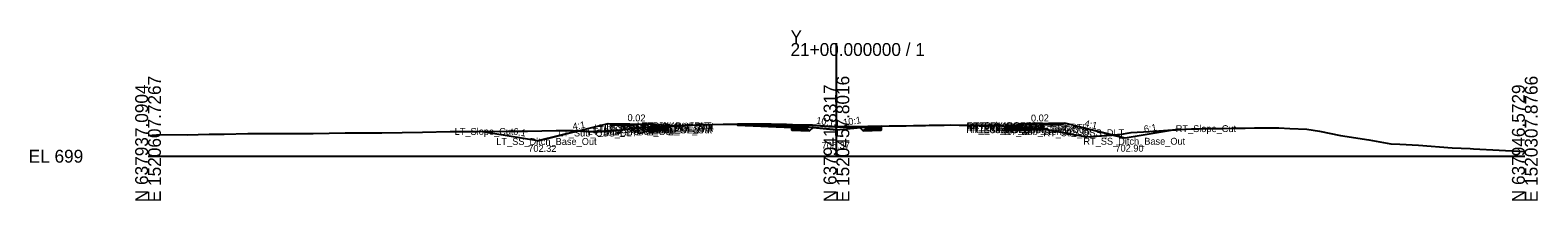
# Model space of a CAD drawing. Extents: x -26 to 303, y -10 to 5039.
# Drawn here: x -25.7 to 302.8, y 4490.3 to 4527.4 of the extents above; entities that cross this region are included whole.
import ezdxf

# ---------------------------------------------------------------- set-up
doc = ezdxf.new("R2010")
doc.units = 0
for name, color, linetype in [('Default', 7, 'Continuous'), ('Exist Cross Section Cell', 7, 'Continuous'), ('Exist XS Center Line Elevation Label', 7, 'Continuous'), ('Exist XS Ground Line', 7, 'Continuous'), ('Prop CMT Pvmt Course 1', 7, 'Continuous'), ('Prop CMT Pvmt Course 2', 7, 'Continuous'), ('Prop CMT Pvmt Course 3', 7, 'Continuous'), ('Prop CMT Pvmt Surface Shoulder', 7, 'Continuous'), ('Prop CMT Shld Paved Course 1', 7, 'Continuous'), ('Prop CMT Shld Paved Course 2', 7, 'Continuous'), ('Prop CMT Shld Paved Course 3', 7, 'Continuous'), ('Prop CMT Slope Grass', 7, 'Continuous'), ('Prop CMT Subgrade Earthwork', 7, 'Continuous'), ('Prop Conc 4in Sidewalk', 7, 'Continuous'), ('Prop XS Ditch Standard Text', 7, 'Continuous'), ('Prop XS Earthwork Shape', 7, 'Continuous'), ('Prop XS Side Slope Text', 7, 'Continuous'), ('Scratch_Level_0', 7, 'Continuous'), ('Typical Curb CELL', 7, 'Continuous'), ('Typical Shoulder Slope Information CELL', 7, 'Continuous')]:
    doc.layers.add(name, color=color, linetype=linetype)

# ---------------------------------------------------------------- blocks, each defined once
blk = doc.blocks.new('2_6 CURB RIGHT')
at = {"layer": 'Typical Curb CELL'}
for p, q in [((0, -0.58), (0, 0)), ((0, 0), (1.75, -0.07)), ((2, 0.17), (2, 0.18)), ((2.5, 0.42), (2.24, 0.42)), ((2.31, 0.08), (2.33, -0.01)), ((2.46, 0.04), (2.31, 0.08)), ((2.33, -0.01), (2.46, 0.04)), ((2.5, -0.58), (2.5, 0.42)), ((2.5, -0.58), (0, -0.58)), ((0.26, -0.34), (0.35, -0.22)), ((0.38, -0.34), (0.26, -0.34)), ((0.35, -0.22), (0.38, -0.34)), ((1.03, -0.39), (1.09, -0.28)), ((1.19, -0.36), (1.03, -0.39)), ((1.09, -0.28), (1.19, -0.36)), ((1.51, -0.34), (1.6, -0.22)), ((1.63, -0.34), (1.51, -0.34)), ((1.6, -0.22), (1.63, -0.34)), ((2.27, -0.39), (2.34, -0.28)), ((2.44, -0.36), (2.27, -0.39)), ((2.34, -0.28), (2.44, -0.36))]:
    blk.add_line(p, q, dxfattribs=at)
for centre in [(2.27, 0.34), (2.43, 0.12), (2.49, 0.31), (0.01, -0.55), (0.02, -0.25), (0.03, -0.15), (0.07, -0.39), (0.09, -0.18), (0.17, -0.34), (0.2, -0.06), (0.22, -0.58), (0.3, -0.14), (0.34, -0.04), (0.38, -0.51), (0.49, -0.1), (0.52, -0.21), (0.59, -0.53), (0.67, -0.29), (0.69, -0.12), (0.7, -0.45), (0.71, -0.07), (0.76, -0.56), (0.79, -0.26), (0.93, -0.5), (0.97, -0.1), (1.09, -0.15), (1.11, -0.54), (1.26, -0.55), (1.27, -0.25), (1.28, -0.15), (1.32, -0.39), (1.34, -0.18), (1.42, -0.34), (1.45, -0.1), (1.47, -0.58), (1.54, -0.14), (1.63, -0.51), (1.74, -0.1), (1.77, -0.21), (1.84, -0.53), (1.92, -0.29), (1.94, -0.12), (1.95, -0.45), (1.96, -0.07), (2.01, -0.56), (2.04, -0.26), (2.18, -0.5), (2.22, -0.1), (2.34, -0.15), (2.35, -0.54)]:
    blk.add_circle(centre, 0.00802, dxfattribs=at)
for centre, start, end in [((1.76, 0.17), 267.6155, 0), ((2.24, 0.18), 90, 180)]:
    blk.add_arc(centre, 0.24, start, end, dxfattribs=at)

msp = doc.modelspace()

# ---------------------------------------------------------------- linework, layer by layer
at = {"layer": 'Exist Cross Section Cell'}
for p, q in [((150, 4500), (150, 4524.61)), ((0, 4500), (150, 4500)), ((150, 4500), (300, 4500))]:
    msp.add_line(p, q, dxfattribs=at)
at = {"layer": 'Exist XS Ground Line'}
msp.add_lwpolyline([(0, 4504.54), (2.72, 4504.71), (8.54, 4504.65), (13.29, 4504.8), (16.55, 4504.83), (21.74, 4504.92), (23.33, 4504.94), (25.09, 4504.94), (36, 4504.94), (42.98, 4505.07), (47.32, 4505.08), (50.96, 4505.1), (59.8, 4505.23), (65.84, 4505.36), (71.63, 4505.4), (78.49, 4505.44), (82.69, 4505.47), (88.9, 4505.58), (92.62, 4505.63), (93.44, 4505.55), (97.09, 4505.29), (100.88, 4505.5), (102.66, 4505.59), (103.48, 4505.72), (107.67, 4506.29), (111.33, 4506.52), (111.72, 4506.54), (112.82, 4506.55), (114.48, 4506.63), (115.17, 4506.63), (117.64, 4506.72), (120.29, 4506.81), (122.9, 4506.89), (125.34, 4506.97), (126.51, 4507), (127.63, 4507), (129.67, 4506.99), (130.12, 4506.98), (130.6, 4506.98), (132.63, 4506.98), (133.21, 4506.97), (135.13, 4506.94), (135.77, 4506.94), (137.63, 4506.92), (138.27, 4506.9), (138.76, 4506.88), (139.15, 4506.87), (140.41, 4506.84), (144.75, 4506.74), (148.25, 4506.5), (149.66, 4506.37), (150, 4506.37), (153.53, 4506.4), (155.77, 4506.4), (156.87, 4506.45), (161.47, 4506.58), (162.07, 4506.58), (162.66, 4506.59), (163.37, 4506.61), (165.18, 4506.63), (166.8, 4506.67), (167.67, 4506.68), (169.38, 4506.71), (170.17, 4506.73), (170.9, 4506.74), (172.66, 4506.77), (173.49, 4506.78), (174.77, 4506.81), (176.73, 4506.78), (177.65, 4506.76), (178.16, 4506.76), (180.15, 4506.74), (182.28, 4506.71), (182.66, 4506.71), (185.23, 4506.67), (186.2, 4506.64), (190.67, 4506.28), (195.28, 4505.91), (202.97, 4504.5), (204.45, 4504.21), (210.31, 4504.63), (211.21, 4504.69), (211.65, 4504.75), (214.25, 4505.13), (218.25, 4505.4), (227.4, 4505.99), (228.06, 4505.99), (228.66, 4505.99), (229.05, 4505.99), (229.84, 4506), (231.08, 4506.01), (231.8, 4506.01), (233.58, 4506.04), (234.23, 4506.05), (236.07, 4506.07), (238.04, 4506.1), (238.57, 4506.11), (239.07, 4506.11), (241.07, 4506.14), (241.43, 4506.15), (243.46, 4506.17), (244.43, 4506.19), (245.49, 4506.19), (246.39, 4506.19), (248.8, 4506.06), (252.52, 4505.88), (255.23, 4505.43), (259.87, 4504.54), (266.01, 4503.59), (270.8, 4502.68), (272.74, 4502.59), (276.85, 4502.38), (284.18, 4501.83), (288.08, 4501.66), (288.82, 4501.62), (300, 4501.02)], dxfattribs=at)
at = {"layer": 'Prop CMT Pvmt Course 1'}
for p, q in [((114, 4506.35), (113.25, 4506.32)), ((114, 4506.35), (114, 4506.6)), ((143.51, 4506.15), (143.25, 4506.41)), ((156.49, 4506.15), (156.75, 4506.41))]:
    msp.add_line(p, q, dxfattribs=at)
for points in [[(113.24, 4506.57), (113.24, 4506.32)], [(113.24, 4506.32), (113.25, 4506.32)], [(113.25, 4506.32), (113.25, 4506.57)], [(140.25, 4506.28), (140.25, 4506.53)], [(159.75, 4506.28), (159.75, 4506.53)], [(186.74, 4506.37), (186.74, 4506.62)]]:
    msp.add_lwpolyline(points, dxfattribs=at)
at = {"layer": 'Prop CMT Pvmt Course 2'}
for points in [[(113.25, 4506.32), (113.24, 4506.32)], [(113.24, 4506.32), (113.24, 4506.07)], [(113.24, 4506.07), (113.25, 4506.07)], [(113.25, 4506.07), (113.25, 4506.32)], [(140.25, 4506.03), (140.25, 4506.28)], [(159.75, 4506.03), (159.75, 4506.28)]]:
    msp.add_lwpolyline(points, dxfattribs=at)
at = {"layer": 'Prop CMT Pvmt Course 3'}
for points in [[(113.25, 4506.07), (113.24, 4506.07)], [(113.24, 4506.07), (113.24, 4505.7)], [(113.24, 4505.7), (113.25, 4505.7)], [(113.25, 4505.7), (113.25, 4506.07)], [(140.25, 4505.66), (140.25, 4506.03)], [(159.74, 4505.65), (159.75, 4505.65)], [(159.75, 4505.66), (159.75, 4506.03)]]:
    msp.add_lwpolyline(points, dxfattribs=at)
at = {"layer": 'Prop CMT Pvmt Surface Shoulder'}
for p, q in [((143.25, 4506.41), (128.41, 4507)), ((156.75, 4506.41), (159.75, 4506.53))]:
    msp.add_line(p, q, dxfattribs=at)
for points in [[(114, 4506.6), (112.24, 4506.53)], [(186.74, 4506.62), (187.75, 4506.58)]]:
    msp.add_lwpolyline(points, dxfattribs=at)
at = {"layer": 'Prop CMT Shld Paved Course 1'}
for points in [[(112.24, 4506.28), (113.25, 4506.32)], [(113.24, 4506.32), (113.24, 4506.57)], [(187.75, 4506.33), (186.74, 4506.37)]]:
    msp.add_lwpolyline(points, dxfattribs=at)
at = {"layer": 'Prop CMT Shld Paved Course 2'}
for p, q in [((143.77, 4505.89), (143.51, 4506.15)), ((156.23, 4505.89), (156.49, 4506.15))]:
    msp.add_line(p, q, dxfattribs=at)
for points in [[(113.25, 4506.32), (112.24, 4506.28)], [(112.24, 4506.03), (113.25, 4506.07)], [(113.24, 4506.07), (113.24, 4506.32)], [(140.25, 4506.28), (143.51, 4506.15)], [(143.77, 4505.89), (140.25, 4506.03)], [(156.23, 4505.89), (159.75, 4506.03)], [(159.75, 4506.28), (156.49, 4506.15)], [(186.74, 4506.37), (187.75, 4506.33)], [(187.75, 4506.08), (186.74, 4506.12)]]:
    msp.add_lwpolyline(points, dxfattribs=at)
at = {"layer": 'Prop CMT Shld Paved Course 3'}
for p, q in [((109.24, 4505.95), (108.81, 4505.52)), ((109.74, 4505.95), (109.24, 4505.95)), ((144.16, 4505.5), (143.77, 4505.89)), ((155.84, 4505.5), (156.23, 4505.89)), ((190.25, 4505.99), (190.75, 4505.99)), ((190.75, 4505.99), (191.18, 4505.57))]:
    msp.add_line(p, q, dxfattribs=at)
for points in [[(108.81, 4505.52), (113.25, 4505.7)], [(113.25, 4506.07), (112.24, 4506.03)], [(113.24, 4505.7), (113.24, 4506.07)], [(140.25, 4506.03), (143.77, 4505.89)], [(144.16, 4505.5), (140.25, 4505.66)], [(155.84, 4505.5), (159.75, 4505.66)], [(159.75, 4506.03), (156.23, 4505.89)], [(186.74, 4506.12), (187.75, 4506.08)], [(191.18, 4505.57), (186.74, 4505.74)]]:
    msp.add_lwpolyline(points, dxfattribs=at)
at = {"layer": 'Prop CMT Slope Grass'}
for p, q in [((84.96, 4503.32), (100.24, 4507.14)), ((100.24, 4507.14), (109.74, 4506.95)), ((150, 4505.74), (143.25, 4506.41)), ((150, 4505.74), (156.75, 4506.41)), ((199.75, 4507.18), (190.25, 4506.99)), ((212.9, 4503.9), (199.75, 4507.18)), ((224.21, 4505.78), (212.9, 4503.9))]:
    msp.add_line(p, q, dxfattribs=at)
msp.add_lwpolyline([(84.96, 4503.32), (72.47, 4505.4)], dxfattribs=at)
at = {"layer": 'Prop CMT Subgrade Earthwork'}
for p, q in [((108.81, 4505.52), (107.34, 4507)), ((109.74, 4505.95), (109.74, 4506.95)), ((112.24, 4505.95), (109.74, 4505.95)), ((112.24, 4506.53), (112.24, 4505.95)), ((114, 4506.35), (113.25, 4506.32)), ((113.25, 4505.7), (113.25, 4506.32)), ((114, 4506.6), (114, 4506.35)), ((128.41, 4506.75), (128.41, 4507)), ((140.25, 4506.28), (128.41, 4506.75)), ((140.25, 4506.28), (140.25, 4505.66)), ((159.75, 4506.53), (159.75, 4505.66)), ((186.74, 4505.74), (186.74, 4506.62)), ((187.75, 4506.58), (190.25, 4506.99)), ((191.18, 4505.57), (192.65, 4507.04))]:
    msp.add_line(p, q, dxfattribs=at)
for points in [[(113.25, 4505.7), (108.81, 4505.52)], [(140.25, 4505.66), (144.16, 4505.5)], [(144.16, 4505.5), (144.91, 4506.24)], [(155.84, 4505.5), (155.09, 4506.24)], [(159.75, 4505.66), (155.84, 4505.5)], [(159.75, 4506.53), (159.75, 4505.65), (159.74, 4505.65)], [(186.74, 4505.74), (191.18, 4505.57)]]:
    msp.add_lwpolyline(points, dxfattribs=at)
at = {"layer": 'Prop Conc 4in Sidewalk'}
for p, q in [((100.74, 4507.13), (100.74, 4506.8)), ((100.74, 4506.8), (105.74, 4506.7)), ((105.74, 4507.03), (105.74, 4506.7)), ((194.25, 4507.07), (194.25, 4506.74)), ((199.25, 4506.84), (194.25, 4506.74)), ((199.25, 4507.17), (199.25, 4506.84))]:
    msp.add_line(p, q, dxfattribs=at)
at = {"layer": 'Prop XS Earthwork Shape'}
for points in [[(82.69, 4505.47), (88.9, 4505.58), (92.62, 4505.63), (93.44, 4505.55), (93.79, 4505.53), (84.96, 4503.32), (72.47, 4505.4), (78.49, 4505.44)], [(100.24, 4507.14), (107.33, 4507), (108.02, 4506.31), (107.67, 4506.29), (103.48, 4505.72), (102.66, 4505.59), (100.88, 4505.5), (97.09, 4505.29), (93.79, 4505.53)], [(114, 4506.35), (113.25, 4506.32), (113.25, 4505.7), (108.81, 4505.52), (108.02, 4506.31), (109.74, 4506.42), (109.74, 4505.95), (112.24, 4505.95), (112.24, 4506.53), (112.58, 4506.55), (112.82, 4506.55), (114, 4506.6)], [(112.24, 4505.95), (109.74, 4505.95), (109.74, 4506.42), (111.33, 4506.52), (111.72, 4506.54), (112.58, 4506.55), (112.24, 4506.53)], [(144.16, 4505.5), (144.91, 4506.24), (143.25, 4506.41), (128.64, 4507), (128.41, 4507), (128.41, 4506.75), (140.25, 4506.28), (140.25, 4505.66)], [(150, 4505.74), (155.09, 4506.24), (156.75, 4506.41), (159.75, 4506.53), (156.87, 4506.45), (155.77, 4506.4), (153.53, 4506.4), (150, 4506.37), (149.66, 4506.37), (148.25, 4506.5), (144.75, 4506.74), (140.41, 4506.84), (139.15, 4506.87), (138.76, 4506.88), (138.27, 4506.9), (137.63, 4506.92), (135.77, 4506.94), (135.13, 4506.94), (133.21, 4506.97), (132.63, 4506.98), (130.6, 4506.98), (130.12, 4506.98), (129.67, 4506.99), (128.64, 4507), (143.25, 4506.41), (144.91, 4506.24)], [(159.75, 4506.53), (159.74, 4505.65), (155.84, 4505.5), (155.09, 4506.24), (156.75, 4506.41)], [(186.74, 4505.74), (191.18, 4505.57), (191.8, 4506.19), (190.67, 4506.28), (186.74, 4506.6)], [(195.28, 4505.91), (202.97, 4504.5), (204.45, 4504.21), (210.03, 4504.61), (199.75, 4507.18), (192.65, 4507.04), (191.8, 4506.19)], [(212.9, 4503.9), (210.03, 4504.61), (210.31, 4504.63), (211.21, 4504.69), (211.65, 4504.75), (214.25, 4505.13), (218.25, 4505.4), (224.21, 4505.78)]]:
    msp.add_lwpolyline(points, close=True, dxfattribs=at)

# ---------------------------------------------------------------- block references
at = {"layer": 'Prop CMT Slope Grass', "yscale": -1, "rotation": 180}
msp.add_blockref('2_6 CURB RIGHT', (112.24, 4506.53), dxfattribs=at)
at = {"layer": 'Prop CMT Slope Grass'}
msp.add_blockref('2_6 CURB RIGHT', (187.75, 4506.58), dxfattribs=at)

# ---------------------------------------------------------------- texts
at = {"layer": 'Default'}
msp.add_text('-', height=0.0001, dxfattribs=at).set_placement((0, 4500))
at = {"layer": 'Exist Cross Section Cell'}
for s, p in [('Y', (140, 4524.61)), ('21+00.000000 / 1', (140, 4521.81)), ('EL 699', (-26, 4498.6))]:
    msp.add_text(s, height=2.8, dxfattribs=at).set_placement(p)
for s, p in [('N 637937.0904', (0, 4490)), ('E 1520607.7267', (2.8, 4490)), ('N 637941.8317', (150, 4490)), ('E 1520457.8016', (152.8, 4490)), ('N 637946.5729', (300, 4490)), ('E 1520307.8766', (302.8, 4490))]:
    msp.add_text(s, height=2.8, rotation=90, dxfattribs=at).set_placement(p)
at = {"layer": 'Exist XS Center Line Elevation Label'}
msp.add_text('705.37', height=1.5, dxfattribs=at).set_placement((146.78, 4501.62))
at = {"layer": 'Prop XS Ditch Standard Text'}
for s, p in [('702.32', (82.85, 4500.95)), ('702.90', (210.79, 4501))]:
    msp.add_text(s, height=1.5, dxfattribs=at).set_placement(p)
at = {"layer": 'Prop XS Side Slope Text'}
for s, rotation, p in [('4:1', 9.4623, (92.62, 4505.71)), ('10:1', 350.5377, (145.51, 4507.11)), ('10:1', 9.4623, (151.61, 4506.57)), ('4:1', 346.7942, (203.91, 4506.48)), ('6:1', 350.5191, (79.48, 4504.72)), ('6:1', 9.4809, (217.12, 4505.14))]:
    msp.add_text(s, height=1.5, rotation=rotation, dxfattribs=at).set_placement(p)
at = {"layer": 'Scratch_Level_0'}
for s, p in [('RT_Sub_Out_DLT', (178.37, 4505.9)), ('LT_Slope_Cut', (66.81, 4504.65)), ('LT_Sub_OSS_DLT', (89.35, 4504.3)), ('LT_Sub_Trench_Out', (95.74, 4504.6)), ('LT_PS3_Shelf_Out', (96.95, 4504.99)), ('LT_GS_OS_CTL', (97.19, 4505.45)), ('LT_PS3_OEOP', (99.15, 4505.01)), ('LT_PS2_OEOP', (99.41, 4505.27)), ('LT_PS1_OEOP', (99.85, 4505.53)), ('LT_PV2_PGL_Out', (106.36, 4505.6)), ('LT_PV3_PGL_Out', (106.36, 4505.35)), ('LT_Sub_PGL_Out', (106.4, 4504.98)), ('LT_Sub_Out_DLT', (106.49, 4505.85)), ('LT_PV1_PGL_Out', (106.54, 4505.85)), ('LT_PV2_OEOT', (107.61, 4505.6)), ('LT_PV3_OEOT', (107.61, 4505.35)), ('LT_Sub_OEOT', (107.64, 4504.98)), ('LT_PV1_OEOT', (107.79, 4505.85)), ('RT_PV2_PGL_Out', (178.27, 4505.65)), ('RT_PV3_PGL_Out', (178.27, 4505.4)), ('RT_Sub_PGL_Out', (178.31, 4505.02)), ('RT_PV1_PGL_Out', (178.45, 4505.9)), ('RT_PV2_OEOT', (179.54, 4505.65)), ('RT_PV3_OEOT', (179.54, 4505.4)), ('RT_Sub_OEOT', (179.57, 4505.02)), ('RT_PV1_OEOT', (179.72, 4505.9)), ('RT_Sub_Trench_Out', (186.5, 4504.65)), ('RT_PS3_Shelf_Out', (186.93, 4505.04)), ('RT_PS1_OEOP', (187.78, 4505.58)), ('RT_PS2_OEOP', (187.86, 4505.32)), ('RT_PS3_OEOP', (188.12, 4505.06)), ('RT_GS_OS_CTL', (189.12, 4505.5)), ('RT_Sub_OSS_DLT', (195.1, 4504.35)), ('RT_Slope_Cut', (223.93, 4505.25)), ('LT_SS_Ditch_Base_Out', (75.88, 4502.45)), ('RT_SS_Ditch_Base_Out', (203.81, 4502.5))]:
    msp.add_text(s, height=1.5, dxfattribs=at).set_placement(p)
at = {"layer": 'Typical Shoulder Slope Information CELL'}
for rotation, p in [(358.8597, (104.47, 4507.64)), (1.1403, (192.4, 4507.53))]:
    msp.add_text('0.02', height=1.5, rotation=rotation, dxfattribs=at).set_placement(p)

doc.saveas('drawing.dxf')
